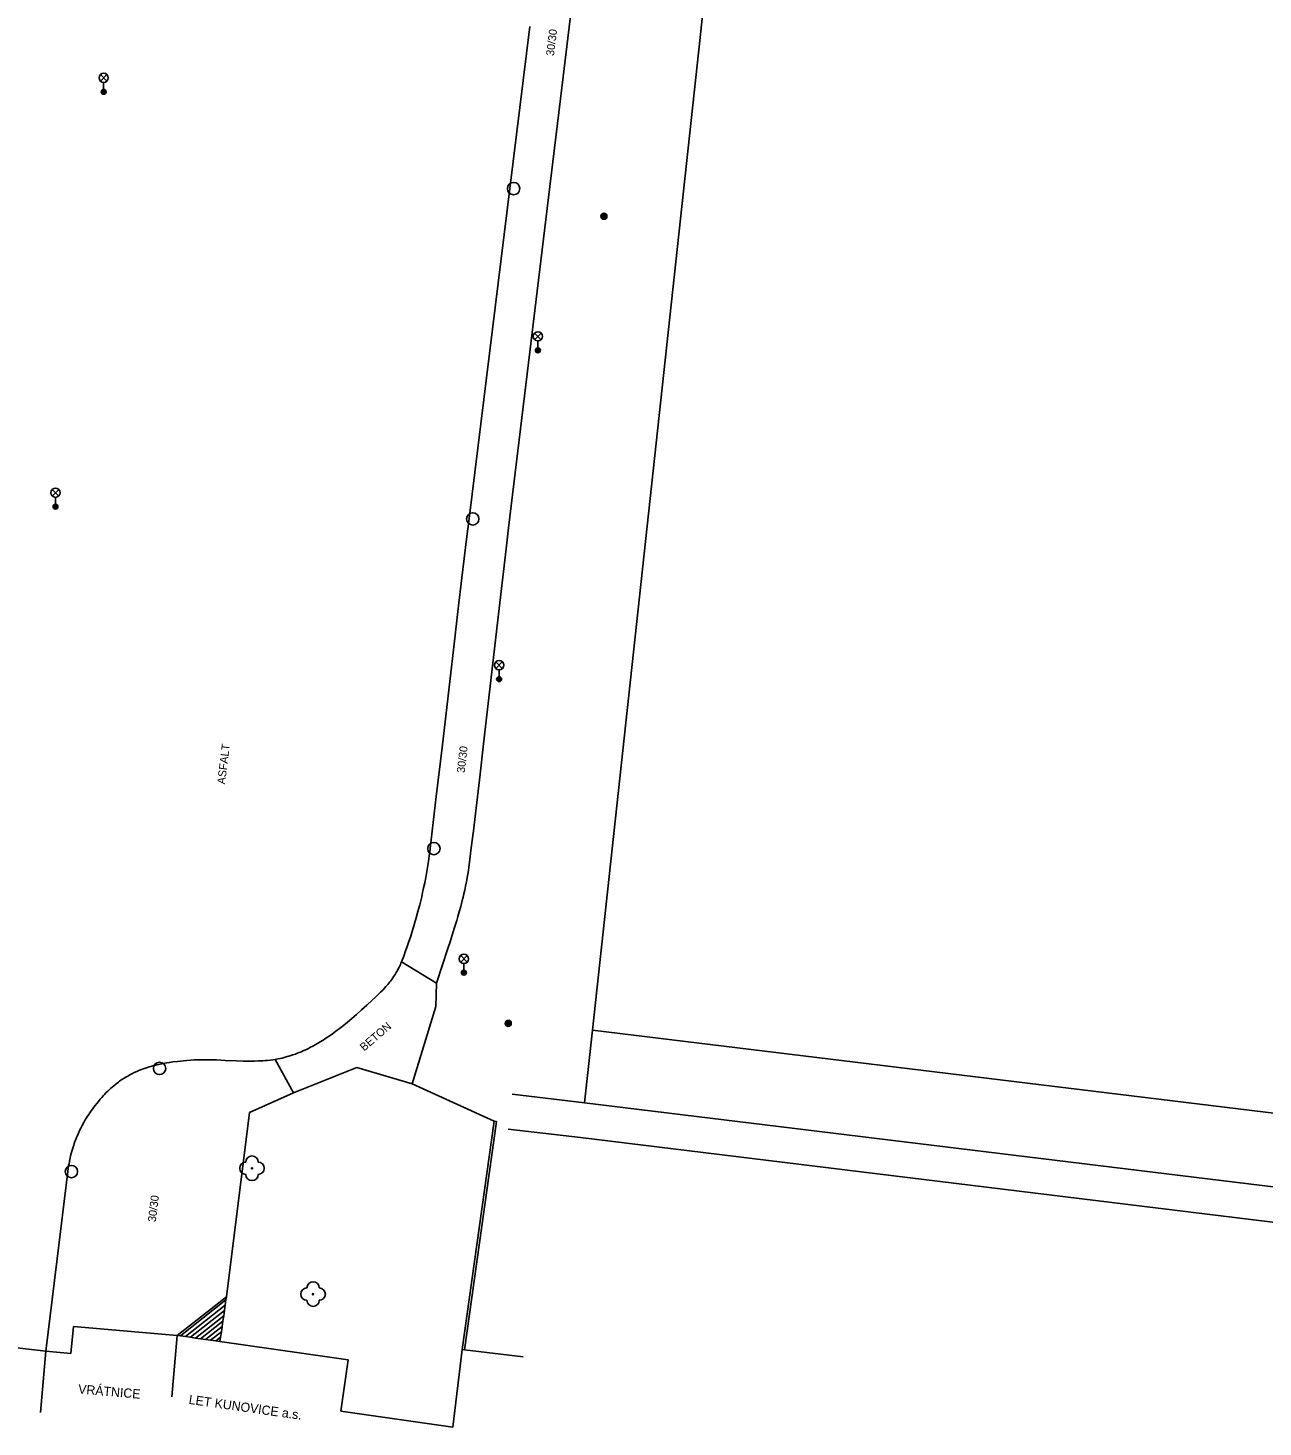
# Model space of a CAD drawing. Extents: x -541281 to -539153, y -1183881 to -1182141.
# Drawn here: x -539780.8 to -539680.5, y -1183402.2 to -1183288.6 of the extents above; entities that cross this region are included whole.
import ezdxf

# ---------------------------------------------------------------- set-up
doc = ezdxf.new("R2010")
doc.units = 0
for name, color, linetype in [('Vrstva 10', 7, 'Continuous'), ('Vrstva 11', 7, 'Continuous'), ('Vrstva 22', 7, 'Continuous'), ('Vrstva 25', 7, 'Continuous'), ('Vrstva 27', 7, 'Continuous'), ('Vrstva 33', 7, 'Continuous'), ('Vrstva 40', 7, 'Continuous'), ('Vrstva 41', 7, 'Continuous'), ('Vrstva 5', 7, 'Continuous'), ('Vrstva 7', 7, 'Continuous'), ('Vrstva 8', 7, 'Continuous')]:
    doc.layers.add(name, color=color, linetype=linetype)

msp = doc.modelspace()

# ---------------------------------------------------------------- linework, layer by layer
at = {"layer": 'Vrstva 10'}
for p, q in [((-539740.08, -1183288.45), (-539740.89, -1183295.02)), ((-539740.89, -1183295.02), (-539741.7, -1183301.59)), ((-539741.7, -1183301.59), (-539743.36, -1183315)), ((-539743.36, -1183315), (-539745.02, -1183328.4)), ((-539745.93, -1183335.96), (-539746.21, -1183338.37)), ((-539746.21, -1183338.37), (-539747.19, -1183346.79)), ((-539777.61, -1183381.45), (-539778.51, -1183388.75)), ((-539778.51, -1183388.75), (-539779.4, -1183396.05))]:
    msp.add_line(p, q, dxfattribs=at)
for points in [[(-539745.02, -1183328.4), (-539745.23, -1183330.07), (-539745.6, -1183333.22), (-539745.93, -1183335.96)], [(-539747.19, -1183346.79), (-539747.68, -1183351), (-539747.93, -1183353.1), (-539748.18, -1183355.21), (-539748.22, -1183355.5), (-539748.25, -1183355.79), (-539748.29, -1183356.06), (-539748.37, -1183356.59)], [(-539748.37, -1183356.59), (-539748.46, -1183357.09), (-539748.54, -1183357.56), (-539748.62, -1183357.99), (-539748.71, -1183358.4), (-539748.79, -1183358.78), (-539748.87, -1183359.13), (-539748.95, -1183359.46), (-539749.03, -1183359.78), (-539749.1, -1183360.07), (-539749.17, -1183360.34), (-539749.31, -1183360.85), (-539749.44, -1183361.3), (-539749.56, -1183361.69), (-539749.67, -1183362.03), (-539749.76, -1183362.33), (-539749.93, -1183362.85), (-539750.07, -1183363.24), (-539750.17, -1183363.53), (-539750.33, -1183363.97), (-539750.5, -1183364.41), (-539750.55, -1183364.53), (-539750.59, -1183364.64), (-539750.64, -1183364.74), (-539750.69, -1183364.84), (-539750.74, -1183364.94), (-539750.83, -1183365.12), (-539750.93, -1183365.29), (-539751.03, -1183365.45), (-539751.12, -1183365.59), (-539751.21, -1183365.72), (-539751.3, -1183365.84), (-539751.38, -1183365.95)], [(-539751.38, -1183365.95), (-539751.46, -1183366.05), (-539751.62, -1183366.25), (-539751.77, -1183366.41)], [(-539751.77, -1183366.41), (-539751.89, -1183366.55), (-539752.01, -1183366.68), (-539752.22, -1183366.89), (-539752.38, -1183367.05), (-539752.63, -1183367.29), (-539752.88, -1183367.53), (-539753.33, -1183367.95), (-539753.76, -1183368.33), (-539754.16, -1183368.69), (-539754.53, -1183369.01)], [(-539754.53, -1183369.01), (-539754.89, -1183369.31), (-539755.22, -1183369.58), (-539755.54, -1183369.83), (-539755.84, -1183370.06), (-539756.12, -1183370.27), (-539756.39, -1183370.45), (-539756.64, -1183370.62), (-539756.88, -1183370.78), (-539757.1, -1183370.92), (-539757.32, -1183371.05), (-539757.52, -1183371.16), (-539757.71, -1183371.27), (-539757.89, -1183371.36), (-539758.06, -1183371.45), (-539758.22, -1183371.53), (-539758.37, -1183371.6), (-539758.51, -1183371.66), (-539758.64, -1183371.72), (-539758.9, -1183371.82), (-539759.12, -1183371.91), (-539759.32, -1183371.98), (-539759.5, -1183372.03), (-539759.65, -1183372.08), (-539759.79, -1183372.12), (-539760.03, -1183372.19), (-539760.21, -1183372.23), (-539760.34, -1183372.26), (-539760.55, -1183372.3), (-539760.76, -1183372.34), (-539760.97, -1183372.37), (-539761.18, -1183372.4), (-539761.38, -1183372.42), (-539761.57, -1183372.44), (-539761.76, -1183372.46), (-539761.95, -1183372.47), (-539762.12, -1183372.47), (-539762.46, -1183372.48), (-539762.79, -1183372.49), (-539763.09, -1183372.49), (-539763.37, -1183372.48)], [(-539763.37, -1183372.48), (-539763.9, -1183372.46), (-539764.83, -1183372.42), (-539765.53, -1183372.39), (-539765.79, -1183372.38), (-539766.02, -1183372.37), (-539766.42, -1183372.37), (-539766.71, -1183372.37), (-539766.94, -1183372.38), (-539767.11, -1183372.38), (-539767.36, -1183372.39), (-539767.61, -1183372.41), (-539767.94, -1183372.44), (-539768.22, -1183372.46), (-539768.47, -1183372.49), (-539768.69, -1183372.51), (-539769.07, -1183372.55), (-539769.36, -1183372.59), (-539769.58, -1183372.63), (-539769.74, -1183372.66), (-539769.98, -1183372.7), (-539770.22, -1183372.75), (-539770.39, -1183372.79), (-539770.56, -1183372.83), (-539770.71, -1183372.87), (-539770.86, -1183372.91), (-539771.01, -1183372.96), (-539771.15, -1183373), (-539771.29, -1183373.05), (-539771.42, -1183373.09), (-539771.54, -1183373.14), (-539771.78, -1183373.23), (-539772, -1183373.33), (-539772.21, -1183373.42), (-539772.4, -1183373.52), (-539772.57, -1183373.61), (-539772.74, -1183373.7), (-539772.89, -1183373.79), (-539773.03, -1183373.88)], [(-539773.03, -1183373.88), (-539773.16, -1183373.96), (-539773.29, -1183374.04), (-539773.4, -1183374.12), (-539773.5, -1183374.2)], [(-539773.5, -1183374.2), (-539773.7, -1183374.35), (-539773.87, -1183374.48), (-539774.01, -1183374.6), (-539774.14, -1183374.72), (-539774.25, -1183374.81), (-539774.34, -1183374.9), (-539774.51, -1183375.06), (-539774.63, -1183375.19), (-539774.72, -1183375.28), (-539774.85, -1183375.43), (-539774.98, -1183375.58), (-539775.12, -1183375.75), (-539775.26, -1183375.92), (-539775.38, -1183376.08), (-539775.5, -1183376.23), (-539775.61, -1183376.38), (-539775.72, -1183376.53), (-539775.82, -1183376.68)], [(-539775.82, -1183376.68), (-539775.91, -1183376.82), (-539776, -1183376.95), (-539776.08, -1183377.08), (-539776.16, -1183377.21), (-539776.31, -1183377.46), (-539776.44, -1183377.7), (-539776.55, -1183377.92), (-539776.65, -1183378.13), (-539776.75, -1183378.33), (-539776.83, -1183378.52), (-539776.9, -1183378.7), (-539776.97, -1183378.86), (-539777.03, -1183379.02), (-539777.08, -1183379.17), (-539777.13, -1183379.3), (-539777.21, -1183379.56), (-539777.28, -1183379.79), (-539777.33, -1183380), (-539777.38, -1183380.18), (-539777.42, -1183380.33), (-539777.47, -1183380.61), (-539777.51, -1183380.82), (-539777.54, -1183380.97), (-539777.58, -1183381.21), (-539777.61, -1183381.45)]]:
    msp.add_lwpolyline(points, dxfattribs=at)
at = {"layer": 'Vrstva 11'}
for p, q in [((-539736.42, -1183284.54), (-539737.49, -1183293.43)), ((-539737.49, -1183293.43), (-539738.57, -1183302.32)), ((-539738.57, -1183302.32), (-539740.19, -1183315.75)), ((-539740.19, -1183315.75), (-539741.81, -1183329.17)), ((-539742.72, -1183336.89), (-539743.84, -1183346.71)), ((-539750.5, -1183364.41), (-539747.66, -1183366.15)), ((-539747.66, -1183366.15), (-539747.73, -1183368.04)), ((-539759.28, -1183375.05), (-539760.76, -1183372.34)), ((-539759.28, -1183375.05), (-539754.14, -1183372.99)), ((-539754.14, -1183372.99), (-539749.64, -1183374.33)), ((-539762.86, -1183376.65), (-539759.28, -1183375.05)), ((-539764.73, -1183391.62), (-539762.86, -1183376.65)), ((-539764.73, -1183391.62), (-539768.72, -1183394.77)), ((-539764.77, -1183391.88), (-539768.47, -1183394.81)), ((-539764.83, -1183392.31), (-539768.06, -1183394.86)), ((-539764.89, -1183392.74), (-539767.65, -1183394.92)), ((-539764.95, -1183393.18), (-539767.24, -1183394.98)), ((-539765.01, -1183393.6), (-539766.83, -1183395.04)), ((-539765.07, -1183394.04), (-539766.42, -1183395.1)), ((-539765.13, -1183394.47), (-539766.01, -1183395.16)), ((-539765.2, -1183394.9), (-539765.6, -1183395.21))]:
    msp.add_line(p, q, dxfattribs=at)
for points in [[(-539741.81, -1183329.17), (-539742.02, -1183330.88), (-539742.39, -1183334.08), (-539742.72, -1183336.89)], [(-539743.84, -1183346.71), (-539744.13, -1183349.17), (-539744.34, -1183351.01), (-539744.67, -1183353.77), (-539744.84, -1183355.15), (-539745.01, -1183356.53)], [(-539745.01, -1183356.53), (-539745.04, -1183356.75), (-539745.07, -1183356.96), (-539745.1, -1183357.16), (-539745.17, -1183357.56), (-539745.23, -1183357.92), (-539745.3, -1183358.27), (-539745.37, -1183358.59), (-539745.44, -1183358.89), (-539745.51, -1183359.17), (-539745.57, -1183359.44), (-539745.7, -1183359.93), (-539745.82, -1183360.36), (-539745.93, -1183360.73), (-539746.02, -1183361.06), (-539746.2, -1183361.63), (-539746.33, -1183362.06), (-539746.54, -1183362.7), (-539746.74, -1183363.34), (-539747.2, -1183364.74), (-539747.66, -1183366.15)], [(-539765.25, -1183395.26), (-539765.2, -1183394.9), (-539765.13, -1183394.47), (-539765.07, -1183394.04), (-539765.01, -1183393.6), (-539764.95, -1183393.18), (-539764.89, -1183392.74), (-539764.83, -1183392.31), (-539764.77, -1183391.88), (-539764.73, -1183391.62)]]:
    msp.add_lwpolyline(points, dxfattribs=at)
at = {"layer": 'Vrstva 22'}
for centre in [(-539762.65, -1183381.19), (-539757.69, -1183391.41)]:
    msp.add_circle(centre, 0.05, dxfattribs=at)
for centre, start, end in [((-539763.15, -1183381.19), 90, 270), ((-539762.65, -1183380.69), 0, 180), ((-539762.15, -1183381.19), 270, 90), ((-539762.65, -1183381.69), 180, 0), ((-539758.19, -1183391.41), 90, 270), ((-539757.69, -1183390.91), 0, 180), ((-539757.19, -1183391.41), 270, 90), ((-539757.69, -1183391.91), 180, 0)]:
    msp.add_arc(centre, 0.5, start, end, dxfattribs=at)
at = {"layer": 'Vrstva 25'}
for centre, radius in [((-539734.07, -1183303.85), 0.25), ((-539734.07, -1183303.85), 0.2), ((-539734.07, -1183303.85), 0.15), ((-539734.07, -1183303.85), 0.1), ((-539734.07, -1183303.85), 0.05), ((-539741.84, -1183369.42), 0.25), ((-539741.84, -1183369.42), 0.2), ((-539741.84, -1183369.42), 0.15), ((-539741.84, -1183369.42), 0.1), ((-539741.84, -1183369.42), 0.05)]:
    msp.add_circle(centre, radius, dxfattribs=at)
at = {"layer": 'Vrstva 27'}
for centre in [(-539741.4, -1183301.61), (-539744.72, -1183328.44), (-539747.88, -1183355.22), (-539770.16, -1183373.07), (-539777.31, -1183381.46)]:
    msp.add_circle(centre, 0.5, dxfattribs=at)
at = {"layer": 'Vrstva 33'}
for p, q in [((-539774.96, -1183292.88), (-539774.44, -1183292.35)), ((-539774.96, -1183292.35), (-539774.44, -1183292.88)), ((-539774.7, -1183292.99), (-539774.7, -1183293.74)), ((-539739.7, -1183313.88), (-539739.17, -1183313.35)), ((-539739.7, -1183313.35), (-539739.17, -1183313.88)), ((-539739.43, -1183313.99), (-539739.43, -1183314.74)), ((-539778.88, -1183326.58), (-539778.34, -1183326.05)), ((-539778.88, -1183326.05), (-539778.34, -1183326.58)), ((-539778.61, -1183326.69), (-539778.61, -1183327.44)), ((-539742.84, -1183340.59), (-539742.32, -1183340.06)), ((-539742.84, -1183340.06), (-539742.32, -1183340.59)), ((-539742.58, -1183340.7), (-539742.58, -1183341.45)), ((-539745.7, -1183364.44), (-539745.18, -1183363.91)), ((-539745.7, -1183363.91), (-539745.18, -1183364.44)), ((-539745.44, -1183364.55), (-539745.44, -1183365.3))]:
    msp.add_line(p, q, dxfattribs=at)
for centre, radius in [((-539774.7, -1183292.61), 0.375), ((-539774.7, -1183293.74), 0.2), ((-539774.7, -1183293.74), 0.145), ((-539774.7, -1183293.74), 0.0876), ((-539739.43, -1183313.61), 0.375), ((-539739.43, -1183314.74), 0.2), ((-539739.43, -1183314.74), 0.145), ((-539739.43, -1183314.74), 0.0876), ((-539778.61, -1183326.31), 0.375), ((-539778.61, -1183327.44), 0.2), ((-539778.61, -1183327.44), 0.145), ((-539778.61, -1183327.44), 0.0876), ((-539742.58, -1183340.32), 0.375), ((-539742.58, -1183341.45), 0.2), ((-539742.58, -1183341.45), 0.145), ((-539742.58, -1183341.45), 0.0876), ((-539745.44, -1183364.18), 0.375), ((-539745.44, -1183365.3), 0.2), ((-539745.44, -1183365.3), 0.145), ((-539745.44, -1183365.3), 0.0876)]:
    msp.add_circle(centre, radius, dxfattribs=at)
at = {"layer": 'Vrstva 5'}
for p, q in [((-539777.35, -1183396.23), (-539777.16, -1183394.05)), ((-539768.72, -1183394.77), (-539777.16, -1183394.05)), ((-539769.15, -1183399.75), (-539768.72, -1183394.77)), ((-539768.72, -1183394.77), (-539768.47, -1183394.81)), ((-539768.47, -1183394.81), (-539768.06, -1183394.86)), ((-539768.06, -1183394.86), (-539767.65, -1183394.92)), ((-539767.65, -1183394.92), (-539767.24, -1183394.98)), ((-539767.24, -1183394.98), (-539766.83, -1183395.04)), ((-539766.83, -1183395.04), (-539766.42, -1183395.1)), ((-539766.42, -1183395.1), (-539766.01, -1183395.16)), ((-539766.01, -1183395.16), (-539765.6, -1183395.21)), ((-539765.6, -1183395.21), (-539765.25, -1183395.26)), ((-539765.25, -1183395.26), (-539754.84, -1183396.74)), ((-539779.82, -1183401.03), (-539779.4, -1183396.05)), ((-539777.35, -1183396.23), (-539779.4, -1183396.05)), ((-539746.34, -1183402.21), (-539745.59, -1183395.91)), ((-539745.39, -1183395.93), (-539745.59, -1183395.91)), ((-539740.62, -1183396.5), (-539745.39, -1183395.93)), ((-539755.43, -1183400.92), (-539754.84, -1183396.74)), ((-539755.43, -1183400.92), (-539746.34, -1183402.21))]:
    msp.add_line(p, q, dxfattribs=at)
at = {"layer": 'Vrstva 7'}
for p, q in [((-539742.99, -1183377.36), (-539749.64, -1183374.33)), ((-539745.59, -1183395.91), (-539742.99, -1183377.36)), ((-539742.99, -1183377.36), (-539742.79, -1183377.39)), ((-539745.39, -1183395.93), (-539742.79, -1183377.39))]:
    msp.add_line(p, q, dxfattribs=at)
for points in [[(-539735.64, -1183375.86), (-539735, -1183369.96), (-539726.24, -1183289.32), (-539718.71, -1183217.87), (-539717.15, -1183202.86)], [(-539559.67, -1183391.26), (-539654.77, -1183379.75), (-539735, -1183369.96)], [(-539741.51, -1183375.18), (-539735.64, -1183375.86), (-539655.75, -1183385.63), (-539560.83, -1183397.22)], [(-539561.17, -1183400.06), (-539629.28, -1183391.74), (-539629.65, -1183394.72), (-539639.38, -1183393.53), (-539639.01, -1183390.55), (-539656.09, -1183388.47), (-539735.98, -1183378.7), (-539741.85, -1183378.02)]]:
    msp.add_lwpolyline(points, dxfattribs=at)
at = {"layer": 'Vrstva 8'}
for p, q in [((-539747.73, -1183368.04), (-539749.64, -1183374.33)), ((-539779.4, -1183396.05), (-539785.32, -1183395.35))]:
    msp.add_line(p, q, dxfattribs=at)

# ---------------------------------------------------------------- texts
at = {"layer": 'Vrstva 40'}
for s, rotation, p in [('30/30', 83.0356, (-539738.13, -1183290.85)), ('ASFALT', 83.0752, (-539764.84, -1183350.02)), ('30/30', 83.3767, (-539745.38, -1183349.09)), ('BETON', 40.8452, (-539753.54, -1183371.71)), ('30/30', 83.0103, (-539770.47, -1183385.58))]:
    msp.add_text(s, height=0.65, rotation=rotation, dxfattribs=at).set_placement(p)
at = {"layer": 'Vrstva 41'}
for s, rotation, p in [('VRÁTNICE', 355.124, (-539776.79, -1183399.48)), ('LET KUNOVICE a.s.', 351.9219, (-539767.82, -1183400.32))]:
    msp.add_text(s, height=0.75, rotation=rotation, dxfattribs=at).set_placement(p)

doc.saveas('drawing.dxf')
